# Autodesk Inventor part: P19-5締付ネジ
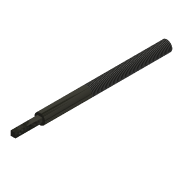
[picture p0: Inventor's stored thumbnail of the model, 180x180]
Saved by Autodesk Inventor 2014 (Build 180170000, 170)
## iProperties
Created: 2008-07
Part Number: P19-5締付ネジ
Document SubType Name: Modeling
Designer: y-shimohigashi
Density: 1 g/cm^3
Stock Number: P19-5締付ネジ
Material: 一般
Appearance: ガンメタル
Author: y-shimohigashi
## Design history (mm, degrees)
sketch "スケッチ2"
  geometry: C1 r 8 at (0, 0); 1 further point
  constraints: 1 centre point, 1 coincident
  dimensions: "d0" = 16 diameter of C1
extrude "押し出し1" new body sketch "スケッチ2" distance "d1" = 190; taper "d2" = 0 deg
sketch "スケッチ3"
  geometry: L1 (3.536, 3.536)-(-3.536, 3.536); L2 (-3.536, 3.536)-(-3.536, -3.536); L3 (-3.536, -3.536)-(3.536, -3.536); L4 (3.536, -3.536)-(3.536, 3.536); L5 (-3.536, 3.536)-(3.536, -3.536); 2 further points
  constraints: 10 end point, 2 parallel, 2 perpendicular, 1 coincident, 1 horizontal, 1 midpoint
  dimensions: "d3" = 10 distance of L1.end L3.end
extrude "押し出し2" join sketch "スケッチ3" distance "d4" = 40; taper "d5" = 0 deg
sketch "スケッチ4"
  geometry: L1 (-86, 0)-(236, 0) reference; L2 (-40, -3.536)-(-40, 3.536) reference; 1 further point
  constraints: 1 point on line
  dimensions: "d6" = 7 distance from line of point (-33, 0) L2
hole "穴1" sketch "スケッチ4" diameter "d7" = 2.459; stored, may be unused: countersink angle "d11" = 90 deg, drill point angle "d13" = 118 deg; dims "d8" = 6, "d9" = 4, "d10" = 2, "d12" = 8
hole "穴2" sketch "スケッチ4" diameter "d14" = 2.459; stored, may be unused: countersink angle "d18" = 90 deg, drill point angle "d20" = 118 deg; dims "d15" = 6, "d16" = 4, "d17" = 2, "d19" = 8
feature "ねじ1" dims "d21" = 120, "d22" = 0
node "ソリッド1"
node "ソリッド ボディ"
node "サーフェス ボディ"
